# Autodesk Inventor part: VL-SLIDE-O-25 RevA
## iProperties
Created: 2007-09
Part Number: VL-SLIDE-O-25 RevA
Material: Steel
Document SubType Name: Modeling
Density: 7.85 g/cm^3
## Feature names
1. Base1
